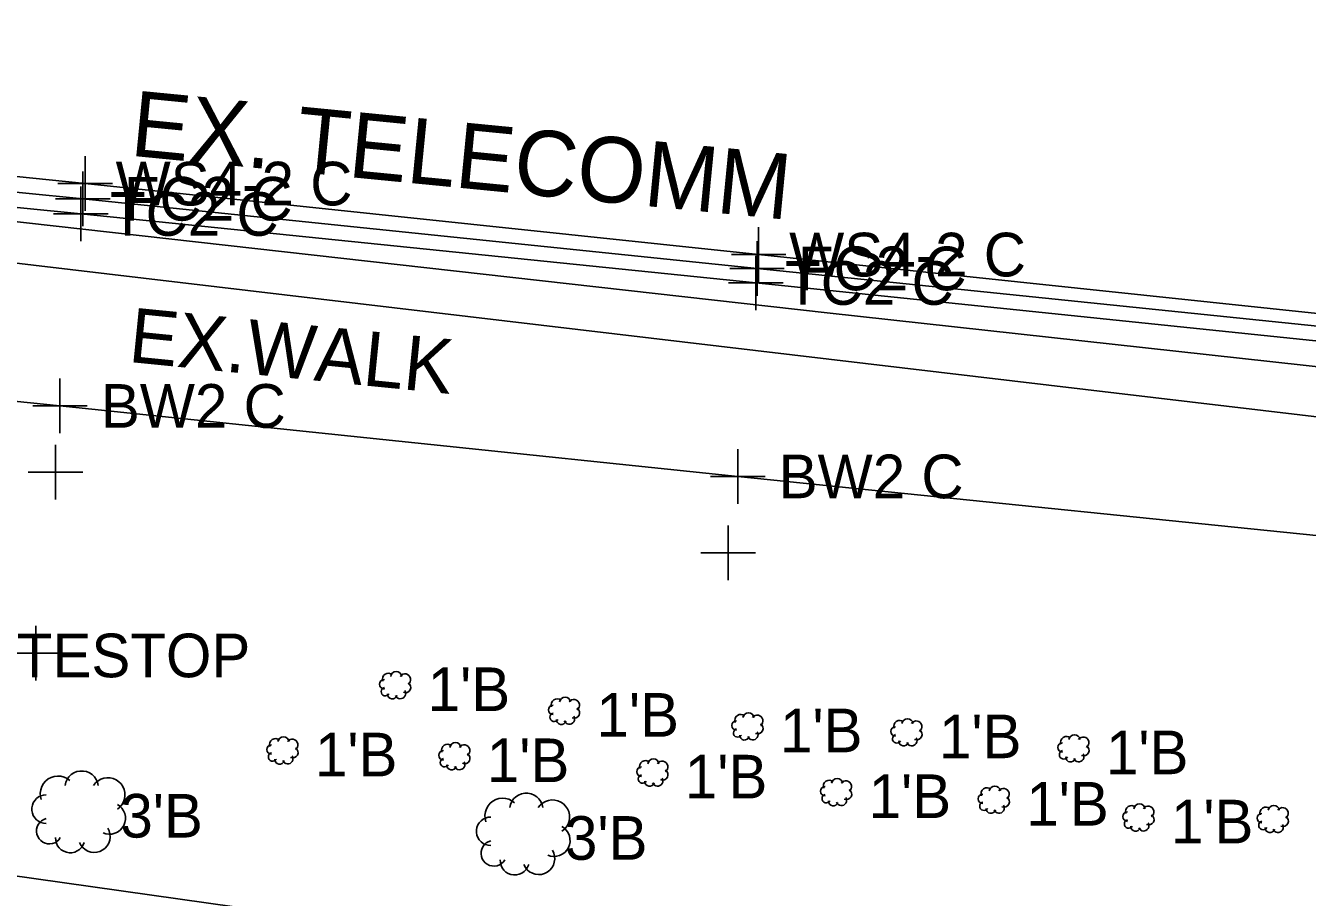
# Model space of a CAD drawing. Extents: x 1363693 to 1365209, y 422201 to 424153.
# Drawn here: x 1363917.01 to 1363963.99, y 423101.26 to 423133.2 of the extents above; entities that cross this region are included whole.
import ezdxf

# ---------------------------------------------------------------- set-up
doc = ezdxf.new("R2010")
doc.units = 0
for name, color, linetype in [('BASELINE-CL-RW', 7, 'Continuous'), ('O-ALGN-TEXT-BASELINE-WERK-CL-RW', 7, 'Continuous'), ('OWNERS', 7, 'Continuous'), ('PM_X_Channelizing_Line', 7, 'Continuous'), ('PM_X_Edge_Line', 7, 'Continuous'), ('RD_X_Text', 7, 'Continuous'), ('SV_X_Original_Ground', 7, 'Continuous'), ('SV_X_Shot_Marker', 7, 'Continuous'), ('UT_X_Electric', 7, 'Continuous'), ('UT_X_Gas', 7, 'Continuous'), ('UT_X_Telecom_FO', 7, 'Continuous'), ('UT_X_Telecom_Text', 7, 'Continuous'), ('VG_X_Cells', 7, 'Continuous'), ('VG_X_Text', 7, 'Continuous')]:
    doc.layers.add(name, color=color, linetype=linetype)

msp = doc.modelspace()

# ---------------------------------------------------------------- linework, layer by layer
at = {"layer": 'BASELINE-CL-RW'}
msp.add_lwpolyline([(1363854.486, 423133.085), (1363869.312, 423131.436), (1363894.671, 423128.722), (1363919.027, 423126.301), (1363943.775, 423123.771), (1363968.892, 423121.174), (1363986.692, 423119.386), (1363988.592, 423118.828), (1363988.592, 423118.828), (1363989.924, 423118.127), (1363989.924, 423118.127), (1363991.614, 423116.848), (1363991.614, 423116.848), (1363992.314, 423116.124), (1363992.314, 423116.124), (1363992.805, 423115.246), (1363992.805, 423115.246), (1363993.14, 423113.905), (1363993.14, 423113.905), (1363993.061, 423112.95), (1363993.061, 423112.95), (1363992.484, 423111.78), (1363992.484, 423111.78), (1363988.886, 423107.661)], dxfattribs=at)
at = {"layer": 'O-ALGN-TEXT-BASELINE-WERK-CL-RW'}
msp.add_lwpolyline([(1363855.331, 423117.197), (1363859.058, 423125.491), (1363868.497, 423124.455), (1363893.383, 423121.812), (1363918.265, 423119.266), (1363943.112, 423116.682), (1363968.025, 423114.135), (1363977.45, 423113.29), (1363978.29, 423106.393), (1363983.735, 423101.689)], dxfattribs=at)
at = {"layer": 'OWNERS'}
msp.add_lwpolyline([(1363854.484, 423133.594), (1363863.975, 423132.591), (1363876.661, 423131.251), (1363894.759, 423129.272), (1363919.107, 423126.857), (1363943.817, 423124.303), (1363968.996, 423121.716), (1363986.701, 423119.906), (1363988.644, 423119.337), (1363990.445, 423118.413), (1363990.445, 423118.413), (1363992.628, 423116.565), (1363992.628, 423116.565)], dxfattribs=at)
at = {"layer": 'PM_X_Channelizing_Line'}
for p, q in [((1363894.772, 423129.921), (1363919.187, 423127.413)), ((1363919.187, 423127.413), (1363943.877, 423124.812)), ((1363943.877, 423124.812), (1363969.07, 423122.159))]:
    msp.add_line(p, q, dxfattribs=at)
at = {"layer": 'PM_X_Edge_Line'}
for p, q in [((1363894.772, 423129.921), (1363919.187, 423127.413)), ((1363919.187, 423127.413), (1363943.877, 423124.812)), ((1363943.877, 423124.812), (1363969.07, 423122.159))]:
    msp.add_line(p, q, dxfattribs=at)
at = {"layer": 'SV_X_Original_Ground'}
for p, q in [((1363919.187, 423126.413), (1363919.187, 423128.413)), ((1363918.187, 423127.413), (1363920.187, 423127.413)), ((1363943.877, 423123.812), (1363943.877, 423125.812)), ((1363942.877, 423124.812), (1363944.877, 423124.812)), ((1363918.098, 423115.841), (1363918.098, 423117.841)), ((1363917.098, 423116.841), (1363919.098, 423116.841)), ((1363942.76, 423112.886), (1363942.76, 423114.886)), ((1363941.76, 423113.886), (1363943.76, 423113.886)), ((1363917.381, 423109.209), (1363917.381, 423111.209)), ((1363916.381, 423110.209), (1363918.381, 423110.209))]:
    msp.add_line(p, q, dxfattribs=at)
at = {"layer": 'SV_X_Shot_Marker'}
for p, q in [((1363919.107, 423125.857), (1363919.107, 423127.857)), ((1363919.027, 423125.301), (1363919.027, 423127.301)), ((1363918.107, 423126.857), (1363920.107, 423126.857)), ((1363918.027, 423126.301), (1363920.027, 423126.301)), ((1363943.817, 423123.303), (1363943.817, 423125.303)), ((1363943.775, 423122.771), (1363943.775, 423124.771)), ((1363942.817, 423124.303), (1363944.817, 423124.303)), ((1363942.775, 423123.771), (1363944.775, 423123.771)), ((1363918.265, 423118.266), (1363918.265, 423120.266)), ((1363917.265, 423119.266), (1363919.265, 423119.266)), ((1363943.112, 423115.682), (1363943.112, 423117.682)), ((1363942.112, 423116.682), (1363944.112, 423116.682))]:
    msp.add_line(p, q, dxfattribs=at)
at = {"layer": 'UT_X_Electric'}
msp.add_lwpolyline([(1363867.968, 423108.916), (1363973.038, 423094.077), (1364006.657, 423093.464)], dxfattribs=at)
at = {"layer": 'UT_X_Gas'}
msp.add_lwpolyline([(1363697.823, 423150.328), (1364024.78, 423111.733), (1364079.651, 423106.56), (1364321.815, 423073.856), (1364574.009, 423047.674), (1364582.932, 423046.282), (1364615.757, 423042.884), (1364684.796, 423035.164)], dxfattribs=at)
at = {"layer": 'UT_X_Telecom_FO'}
for p, q in [((1363858.609, 423132.532), (1363946.389, 423122.683)), ((1363946.389, 423122.683), (1364105.47, 423105.108))]:
    msp.add_line(p, q, dxfattribs=at)
at = {"layer": 'VG_X_Cells'}
for points in [[(1363918.626, 423105.535), (1363918.528, 423105.609), (1363918.418, 423105.663), (1363918.3, 423105.695), (1363918.178, 423105.704), (1363918.056, 423105.69), (1363917.94, 423105.653), (1363917.832, 423105.595), (1363917.737, 423105.518), (1363917.658, 423105.424), (1363917.598, 423105.317), (1363917.56, 423105.201), (1363917.544, 423105.08), (1363917.551, 423104.957), (1363917.581, 423104.839)], [(1363919.671, 423105.361), (1363919.644, 423105.475), (1363919.595, 423105.582), (1363919.527, 423105.677), (1363919.443, 423105.758), (1363919.344, 423105.821), (1363919.235, 423105.865), (1363919.12, 423105.887), (1363919.003, 423105.887), (1363918.888, 423105.865), (1363918.779, 423105.821), (1363918.681, 423105.758), (1363918.596, 423105.677), (1363918.528, 423105.582), (1363918.48, 423105.475), (1363918.452, 423105.361)], [(1363920.368, 423104.491), (1363920.459, 423104.564), (1363920.534, 423104.653), (1363920.592, 423104.754), (1363920.63, 423104.865), (1363920.647, 423104.98), (1363920.642, 423105.097), (1363920.616, 423105.211), (1363920.569, 423105.317), (1363920.503, 423105.414), (1363920.42, 423105.496), (1363920.324, 423105.562), (1363920.217, 423105.609), (1363920.103, 423105.635), (1363919.987, 423105.64), (1363919.871, 423105.623), (1363919.761, 423105.585), (1363919.66, 423105.527), (1363919.571, 423105.452), (1363919.497, 423105.361)], [(1363917.756, 423105.013), (1363917.659, 423105.004), (1363917.567, 423104.978), (1363917.48, 423104.935), (1363917.404, 423104.877), (1363917.339, 423104.805), (1363917.288, 423104.723), (1363917.253, 423104.633), (1363917.235, 423104.539), (1363917.235, 423104.442), (1363917.253, 423104.348), (1363917.288, 423104.258), (1363917.339, 423104.176), (1363917.404, 423104.104), (1363917.48, 423104.046), (1363917.567, 423104.003), (1363917.659, 423103.977), (1363917.756, 423103.968)], [(1363935.969, 423104.548), (1363935.942, 423104.662), (1363935.893, 423104.769), (1363935.825, 423104.864), (1363935.741, 423104.945), (1363935.642, 423105.008), (1363935.533, 423105.052), (1363935.418, 423105.074), (1363935.301, 423105.074), (1363935.186, 423105.052), (1363935.077, 423105.008), (1363934.979, 423104.945), (1363934.894, 423104.864), (1363934.826, 423104.769), (1363934.778, 423104.662), (1363934.75, 423104.548)], [(1363919.845, 423103.62), (1363919.951, 423103.585), (1363920.061, 423103.57), (1363920.172, 423103.577), (1363920.28, 423103.604), (1363920.38, 423103.652), (1363920.47, 423103.717), (1363920.546, 423103.799), (1363920.605, 423103.893), (1363920.645, 423103.997), (1363920.665, 423104.106), (1363920.663, 423104.217), (1363920.641, 423104.326), (1363920.598, 423104.429), (1363920.537, 423104.522), (1363920.459, 423104.601), (1363920.368, 423104.665)], [(1363934.924, 423104.722), (1363934.826, 423104.796), (1363934.716, 423104.85), (1363934.598, 423104.882), (1363934.476, 423104.891), (1363934.354, 423104.877), (1363934.238, 423104.84), (1363934.13, 423104.782), (1363934.035, 423104.705), (1363933.956, 423104.611), (1363933.896, 423104.504), (1363933.858, 423104.388), (1363933.842, 423104.267), (1363933.849, 423104.144), (1363933.879, 423104.026)], [(1363936.666, 423103.678), (1363936.757, 423103.751), (1363936.832, 423103.84), (1363936.89, 423103.941), (1363936.928, 423104.052), (1363936.945, 423104.167), (1363936.94, 423104.284), (1363936.914, 423104.398), (1363936.867, 423104.504), (1363936.801, 423104.601), (1363936.718, 423104.683), (1363936.622, 423104.749), (1363936.515, 423104.796), (1363936.401, 423104.822), (1363936.285, 423104.827), (1363936.169, 423104.81), (1363936.059, 423104.772), (1363935.958, 423104.714), (1363935.869, 423104.639), (1363935.795, 423104.548)], [(1363917.756, 423104.142), (1363917.669, 423104.11), (1363917.59, 423104.063), (1363917.522, 423104), (1363917.468, 423103.926), (1363917.429, 423103.842), (1363917.407, 423103.753), (1363917.403, 423103.66), (1363917.417, 423103.569), (1363917.449, 423103.483), (1363917.497, 423103.404), (1363917.559, 423103.336), (1363917.633, 423103.281), (1363917.717, 423103.242), (1363917.806, 423103.22), (1363917.898, 423103.216), (1363917.99, 423103.23), (1363918.076, 423103.261), (1363918.155, 423103.309), (1363918.223, 423103.371), (1363918.278, 423103.446)], [(1363934.054, 423104.2), (1363933.957, 423104.191), (1363933.865, 423104.165), (1363933.778, 423104.122), (1363933.702, 423104.064), (1363933.637, 423103.992), (1363933.586, 423103.91), (1363933.551, 423103.82), (1363933.533, 423103.726), (1363933.533, 423103.629), (1363933.551, 423103.535), (1363933.586, 423103.445), (1363933.637, 423103.363), (1363933.702, 423103.291), (1363933.778, 423103.233), (1363933.865, 423103.19), (1363933.957, 423103.164), (1363934.054, 423103.155)], [(1363918.975, 423103.271), (1363919.027, 423103.17), (1363919.098, 423103.081), (1363919.185, 423103.007), (1363919.284, 423102.952), (1363919.392, 423102.917), (1363919.506, 423102.903), (1363919.619, 423102.912), (1363919.729, 423102.942), (1363919.831, 423102.993), (1363919.921, 423103.062), (1363919.996, 423103.148), (1363920.053, 423103.247), (1363920.089, 423103.355), (1363920.105, 423103.467), (1363920.098, 423103.581), (1363920.069, 423103.691), (1363920.02, 423103.794)], [(1363936.143, 423102.807), (1363936.249, 423102.772), (1363936.359, 423102.757), (1363936.47, 423102.764), (1363936.578, 423102.791), (1363936.678, 423102.839), (1363936.768, 423102.904), (1363936.844, 423102.986), (1363936.903, 423103.08), (1363936.943, 423103.184), (1363936.963, 423103.293), (1363936.961, 423103.404), (1363936.939, 423103.513), (1363936.896, 423103.616), (1363936.835, 423103.709), (1363936.757, 423103.788), (1363936.666, 423103.852)], [(1363918.104, 423103.446), (1363918.11, 423103.343), (1363918.135, 423103.243), (1363918.179, 423103.15), (1363918.24, 423103.068), (1363918.315, 423102.998), (1363918.403, 423102.944), (1363918.499, 423102.908), (1363918.601, 423102.891), (1363918.703, 423102.894), (1363918.804, 423102.917), (1363918.898, 423102.958), (1363918.982, 423103.016), (1363919.054, 423103.09), (1363919.11, 423103.176), (1363919.149, 423103.271)], [(1363934.054, 423103.329), (1363933.967, 423103.297), (1363933.888, 423103.25), (1363933.82, 423103.187), (1363933.766, 423103.113), (1363933.727, 423103.029), (1363933.705, 423102.94), (1363933.701, 423102.847), (1363933.715, 423102.756), (1363933.747, 423102.67), (1363933.795, 423102.591), (1363933.857, 423102.523), (1363933.931, 423102.468), (1363934.015, 423102.429), (1363934.104, 423102.407), (1363934.196, 423102.403), (1363934.288, 423102.417), (1363934.374, 423102.448), (1363934.453, 423102.496), (1363934.521, 423102.558), (1363934.576, 423102.633)], [(1363935.273, 423102.458), (1363935.325, 423102.357), (1363935.396, 423102.268), (1363935.483, 423102.194), (1363935.582, 423102.139), (1363935.69, 423102.104), (1363935.804, 423102.09), (1363935.917, 423102.099), (1363936.027, 423102.129), (1363936.129, 423102.18), (1363936.219, 423102.249), (1363936.294, 423102.335), (1363936.351, 423102.434), (1363936.387, 423102.542), (1363936.403, 423102.654), (1363936.396, 423102.768), (1363936.367, 423102.878), (1363936.318, 423102.981)], [(1363934.402, 423102.633), (1363934.408, 423102.53), (1363934.433, 423102.43), (1363934.477, 423102.337), (1363934.538, 423102.255), (1363934.613, 423102.185), (1363934.701, 423102.131), (1363934.797, 423102.095), (1363934.899, 423102.078), (1363935.001, 423102.081), (1363935.102, 423102.104), (1363935.196, 423102.145), (1363935.28, 423102.203), (1363935.352, 423102.277), (1363935.408, 423102.363), (1363935.447, 423102.458)]]:
    msp.add_lwpolyline(points, dxfattribs=at)
for centre, radius, start, end in [((1363930.156, 423109.065), 0.174, 90, 270), ((1363930.301, 423109.253), 0.216, 47.7263, 199.6538), ((1363930.591, 423109.326), 0.205, 8.1301, 171.8699), ((1363930.911, 423109.239), 0.209, 303.6901, 146.3099), ((1363930.195, 423108.796), 0.157, 104.4898, 329.25), ((1363930.744, 423108.731), 0.195, 201.8014, 31.3287), ((1363930.931, 423108.953), 0.195, 246.1613, 60.7086), ((1363930.45, 423108.709), 0.178, 177.6627, 343.4127), ((1363936.345, 423108.127), 0.174, 90, 270), ((1363936.49, 423108.315), 0.216, 47.7263, 199.6538), ((1363936.78, 423108.388), 0.205, 8.1301, 171.8699), ((1363937.1, 423108.301), 0.209, 303.6901, 146.3099), ((1363936.384, 423107.858), 0.157, 104.4898, 329.25), ((1363936.933, 423107.793), 0.195, 201.8014, 31.3287), ((1363937.12, 423108.015), 0.195, 246.1613, 60.7086), ((1363943.216, 423107.743), 0.216, 47.7263, 199.6538), ((1363943.506, 423107.816), 0.205, 8.1301, 171.8699), ((1363943.826, 423107.729), 0.209, 303.6901, 146.3099), ((1363936.639, 423107.771), 0.178, 177.6627, 343.4127), ((1363943.071, 423107.555), 0.174, 90, 270), ((1363943.11, 423107.286), 0.157, 104.4898, 329.25), ((1363943.846, 423107.443), 0.195, 246.1613, 60.7086), ((1363948.899, 423107.338), 0.174, 90, 270), ((1363949.044, 423107.526), 0.216, 47.7263, 199.6538), ((1363949.334, 423107.599), 0.205, 8.1301, 171.8699), ((1363949.654, 423107.512), 0.209, 303.6901, 146.3099), ((1363949.674, 423107.226), 0.195, 246.1613, 60.7086), ((1363926.168, 423106.861), 0.216, 47.7263, 199.6538), ((1363926.458, 423106.934), 0.205, 8.1301, 171.8699), ((1363926.778, 423106.847), 0.209, 303.6901, 146.3099), ((1363932.76, 423106.723), 0.205, 8.1301, 171.8699), ((1363943.365, 423107.199), 0.178, 177.6627, 343.4127), ((1363943.659, 423107.221), 0.195, 201.8014, 31.3287), ((1363948.938, 423107.069), 0.157, 104.4898, 329.25), ((1363949.193, 423106.982), 0.178, 177.6627, 343.4127), ((1363949.487, 423107.004), 0.195, 201.8014, 31.3287), ((1363955.019, 423106.751), 0.174, 90, 270), ((1363955.164, 423106.939), 0.216, 47.7263, 199.6538), ((1363955.454, 423107.012), 0.205, 8.1301, 171.8699), ((1363955.774, 423106.925), 0.209, 303.6901, 146.3099), ((1363926.023, 423106.673), 0.174, 90, 270), ((1363926.062, 423106.404), 0.157, 104.4898, 329.25), ((1363926.611, 423106.339), 0.195, 201.8014, 31.3287), ((1363926.798, 423106.561), 0.195, 246.1613, 60.7086), ((1363932.325, 423106.462), 0.174, 90, 270), ((1363932.47, 423106.65), 0.216, 47.7263, 199.6538), ((1363933.08, 423106.636), 0.209, 303.6901, 146.3099), ((1363933.1, 423106.35), 0.195, 246.1613, 60.7086), ((1363955.058, 423106.482), 0.157, 104.4898, 329.25), ((1363955.607, 423106.417), 0.195, 201.8014, 31.3287), ((1363955.794, 423106.639), 0.195, 246.1613, 60.7086), ((1363926.317, 423106.317), 0.178, 177.6627, 343.4127), ((1363932.364, 423106.193), 0.157, 104.4898, 329.25), ((1363932.619, 423106.106), 0.178, 177.6627, 343.4127), ((1363932.913, 423106.128), 0.195, 201.8014, 31.3287), ((1363939.584, 423105.863), 0.174, 90, 270), ((1363939.729, 423106.051), 0.216, 47.7263, 199.6538), ((1363940.019, 423106.124), 0.205, 8.1301, 171.8699), ((1363940.339, 423106.037), 0.209, 303.6901, 146.3099), ((1363955.313, 423106.395), 0.178, 177.6627, 343.4127), ((1363939.623, 423105.594), 0.157, 104.4898, 329.25), ((1363939.878, 423105.507), 0.178, 177.6627, 343.4127), ((1363940.172, 423105.529), 0.195, 201.8014, 31.3287), ((1363940.359, 423105.751), 0.195, 246.1613, 60.7086), ((1363946.465, 423105.334), 0.216, 47.7263, 199.6538), ((1363946.755, 423105.407), 0.205, 8.1301, 171.8699), ((1363947.075, 423105.32), 0.209, 303.6901, 146.3099), ((1363946.32, 423105.146), 0.174, 90, 270), ((1363946.359, 423104.877), 0.157, 104.4898, 329.25), ((1363947.095, 423105.034), 0.195, 246.1613, 60.7086), ((1363952.099, 423104.868), 0.174, 90, 270), ((1363952.244, 423105.056), 0.216, 47.7263, 199.6538), ((1363952.534, 423105.129), 0.205, 8.1301, 171.8699), ((1363952.854, 423105.042), 0.209, 303.6901, 146.3099), ((1363946.614, 423104.79), 0.178, 177.6627, 343.4127), ((1363946.908, 423104.812), 0.195, 201.8014, 31.3287), ((1363952.138, 423104.599), 0.157, 104.4898, 329.25), ((1363952.687, 423104.534), 0.195, 201.8014, 31.3287), ((1363952.874, 423104.756), 0.195, 246.1613, 60.7086), ((1363957.546, 423104.405), 0.216, 47.7263, 199.6538), ((1363957.836, 423104.478), 0.205, 8.1301, 171.8699), ((1363958.156, 423104.391), 0.209, 303.6901, 146.3099), ((1363962.471, 423104.35), 0.216, 47.7263, 199.6538), ((1363962.761, 423104.423), 0.205, 8.1301, 171.8699), ((1363963.081, 423104.336), 0.209, 303.6901, 146.3099), ((1363952.393, 423104.512), 0.178, 177.6627, 343.4127), ((1363957.401, 423104.217), 0.174, 90, 270), ((1363957.44, 423103.948), 0.157, 104.4898, 329.25), ((1363958.176, 423104.105), 0.195, 246.1613, 60.7086), ((1363962.326, 423104.162), 0.174, 90, 270), ((1363963.101, 423104.05), 0.195, 246.1613, 60.7086), ((1363957.695, 423103.861), 0.178, 177.6627, 343.4127), ((1363957.989, 423103.883), 0.195, 201.8014, 31.3287), ((1363962.365, 423103.893), 0.157, 104.4898, 329.25), ((1363962.62, 423103.806), 0.178, 177.6627, 343.4127), ((1363962.914, 423103.828), 0.195, 201.8014, 31.3287)]:
    msp.add_arc(centre, radius, start, end, dxfattribs=at)

# ---------------------------------------------------------------- texts
at = {"layer": 'RD_X_Text'}
msp.add_text('EX.WALK', height=2, rotation=354.3031, dxfattribs=at).set_placement((1363920.741, 423120.882))
at = {"layer": 'SV_X_Original_Ground'}
for s, p in [('WS4-2 C', (1363920.306, 423126.613)), ('WS4-2 C', (1363944.996, 423124.012)), ('GATESTOP', (1363913.592, 423109.322))]:
    msp.add_text(s, height=1.6, dxfattribs=at).set_placement(p)
at = {"layer": 'SV_X_Shot_Marker'}
for s, p in [('FC2 C', (1363920.607, 423126.057)), ('TC2 C', (1363920.098, 423125.501)), ('FC2 C', (1363945.317, 423123.503)), ('TC2 C', (1363944.846, 423122.971)), ('BW2 C', (1363919.765, 423118.466)), ('BW2 C', (1363944.612, 423115.882))]:
    msp.add_text(s, height=1.6, dxfattribs=at).set_placement(p)
at = {"layer": 'UT_X_Telecom_Text'}
msp.add_text('EX. TELECOMM', height=2.4, rotation=354.4298, dxfattribs=at).set_placement((1363920.799, 423128.44))
at = {"layer": 'VG_X_Text'}
for s, p in [("1'B", (1363931.744, 423108.082)), ("1'B", (1363937.933, 423107.144)), ("1'B", (1363944.659, 423106.572)), ("1'B", (1363950.487, 423106.355)), ("1'B", (1363956.607, 423105.768)), ("1'B", (1363927.611, 423105.69)), ("1'B", (1363933.913, 423105.479)), ("1'B", (1363941.172, 423104.88)), ("1'B", (1363947.908, 423104.163)), ("1'B", (1363953.687, 423103.885)), ("3'B", (1363920.479, 423103.447)), ("1'B", (1363958.989, 423103.234)), ("3'B", (1363936.777, 423102.634))]:
    msp.add_text(s, height=1.6, dxfattribs=at).set_placement(p)

doc.saveas('drawing.dxf')
